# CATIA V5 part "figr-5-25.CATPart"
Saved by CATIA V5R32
Part number: Part2
Bounding box of the stored display mesh (mm): x -75 to 75, y -62.5 to 62.5, z 0 to 20
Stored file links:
  D:\PROJECTS\Project 2022\CATIA V5 6R 2022\Resources\Part Files\c05_catia_v5_6r2022_prt\figr-5-25.CATPart
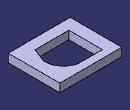
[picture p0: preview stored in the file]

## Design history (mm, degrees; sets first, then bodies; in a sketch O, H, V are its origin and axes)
Body1 (main body)
  Sketch1 on xy-plane, origin (0, 0, 0), H (1, 0, 0), V (0, 1, 0)
    line L1 (-75, 62.5) -> (75, 62.5)
    line L2 (75, 62.5) -> (75, -62.5)
    line L3 (75, -62.5) -> (-75, -62.5)
    line L4 (-75, -62.5) -> (-75, 62.5)
    axis line L5 (75, -62.5) -> (-75, 62.5)
    length L3 = 150
    length L2 = 125
    horizontal: L1 H, L3 H
    vertical: L2 V, L4 V
    midpoint: O L5
  Pad1: profile Sketch1, direction (0, 0, 1), length 20
  Sketch2 on face of Pad1, origin (0, 0, 20), H (1, 0, 0), V (0, 1, 0)
    point P1 (-46.6075, -37.2048)
    line L1 (-46.6075, -37.2048) -> (35.3732, -37.2048)
    point P2 (35.3732, -37.2048)
    point P3 (48.2962, -4.0895)
    line L2 (48.2962, -4.0895) -> (48.2962, 0)
    point P4 (48.2962, 0)
    arc A1 centre (3.919, 0) radius 44.3773 from (48.2962, 0) to (9.9309, 43.9682) ccw
    point P5 (3.919, 0)
    point P6 (9.9309, 43.9682)
    line L3 (9.9309, 43.9682) -> (-46.6075, 43.9682)
    point P7 (-46.6075, 43.9682)
    line L4 (-46.6075, 43.9682) -> (-46.6075, -37.2048)
    line L5 (35.3732, -37.2048) -> (48.2962, -4.0895)
    horizontal: L1 H, L3 H
    coincidence: P4 H
    vertical: L2 V, L4 V
    tangency: A1 L2
    fix: P1, P2, P3, P4, P5, P6, P7, L1, L2, A1, L3, L4, L5
  Pocket1: profile Sketch2, direction (0, 0, -1), through (limit type 3)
